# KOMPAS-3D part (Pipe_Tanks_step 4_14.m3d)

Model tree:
1. X Axis
2. Y Axis
3. Z Axis  (labels: Bend 90 Dn 150; Pipe Dn 150)
     Òîëùèíà ñòåíêè 1 = 1

Referenced files in C:\Documents and Settings\kashirsky\Мои документы\Camtasia Studio\Pipelines3D\Tanks\: Tanks_step 4.a3d
Referenced files in C:\Program Files\ASCON\KOMPAS-3D V10\Libs\Piping\LOAD\: Piping_C_Pipe_150_1000.m3d
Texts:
  Pipe Dn 150
  Steel ASTM A295
  Three Point Plane
  Plane at Angle
  Line and Point Plane
  Axis through Two Vertices
  Axis of Feature
  Axis of Conical Surface
  Axis through Edge
  Trim by Surface
  Trim by Sketch
  Feature with No History
  Intersection Axis of Two Planes
  Two Line Plane
  Line and Face Plane
  Bend by line
  Hole in sheet body
  Cut in sheet body
  Point in CM
  Linear Dimension from Line to Point
  Surface Finish Symbol
  Geometric Tolerance Symbol
  Leader #1
  Leader #2
  Leader #3
  Shape Deviations and Datum
  Node point number
  Mark of coordination axis
  Node point designation
  Mark/Reference designation with leader
  Mark/reference designation on line
  Mark/Reference designation without leader
  Bend 90 Dn 150
  Plane of section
